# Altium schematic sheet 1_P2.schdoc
size 426 x 302 mm
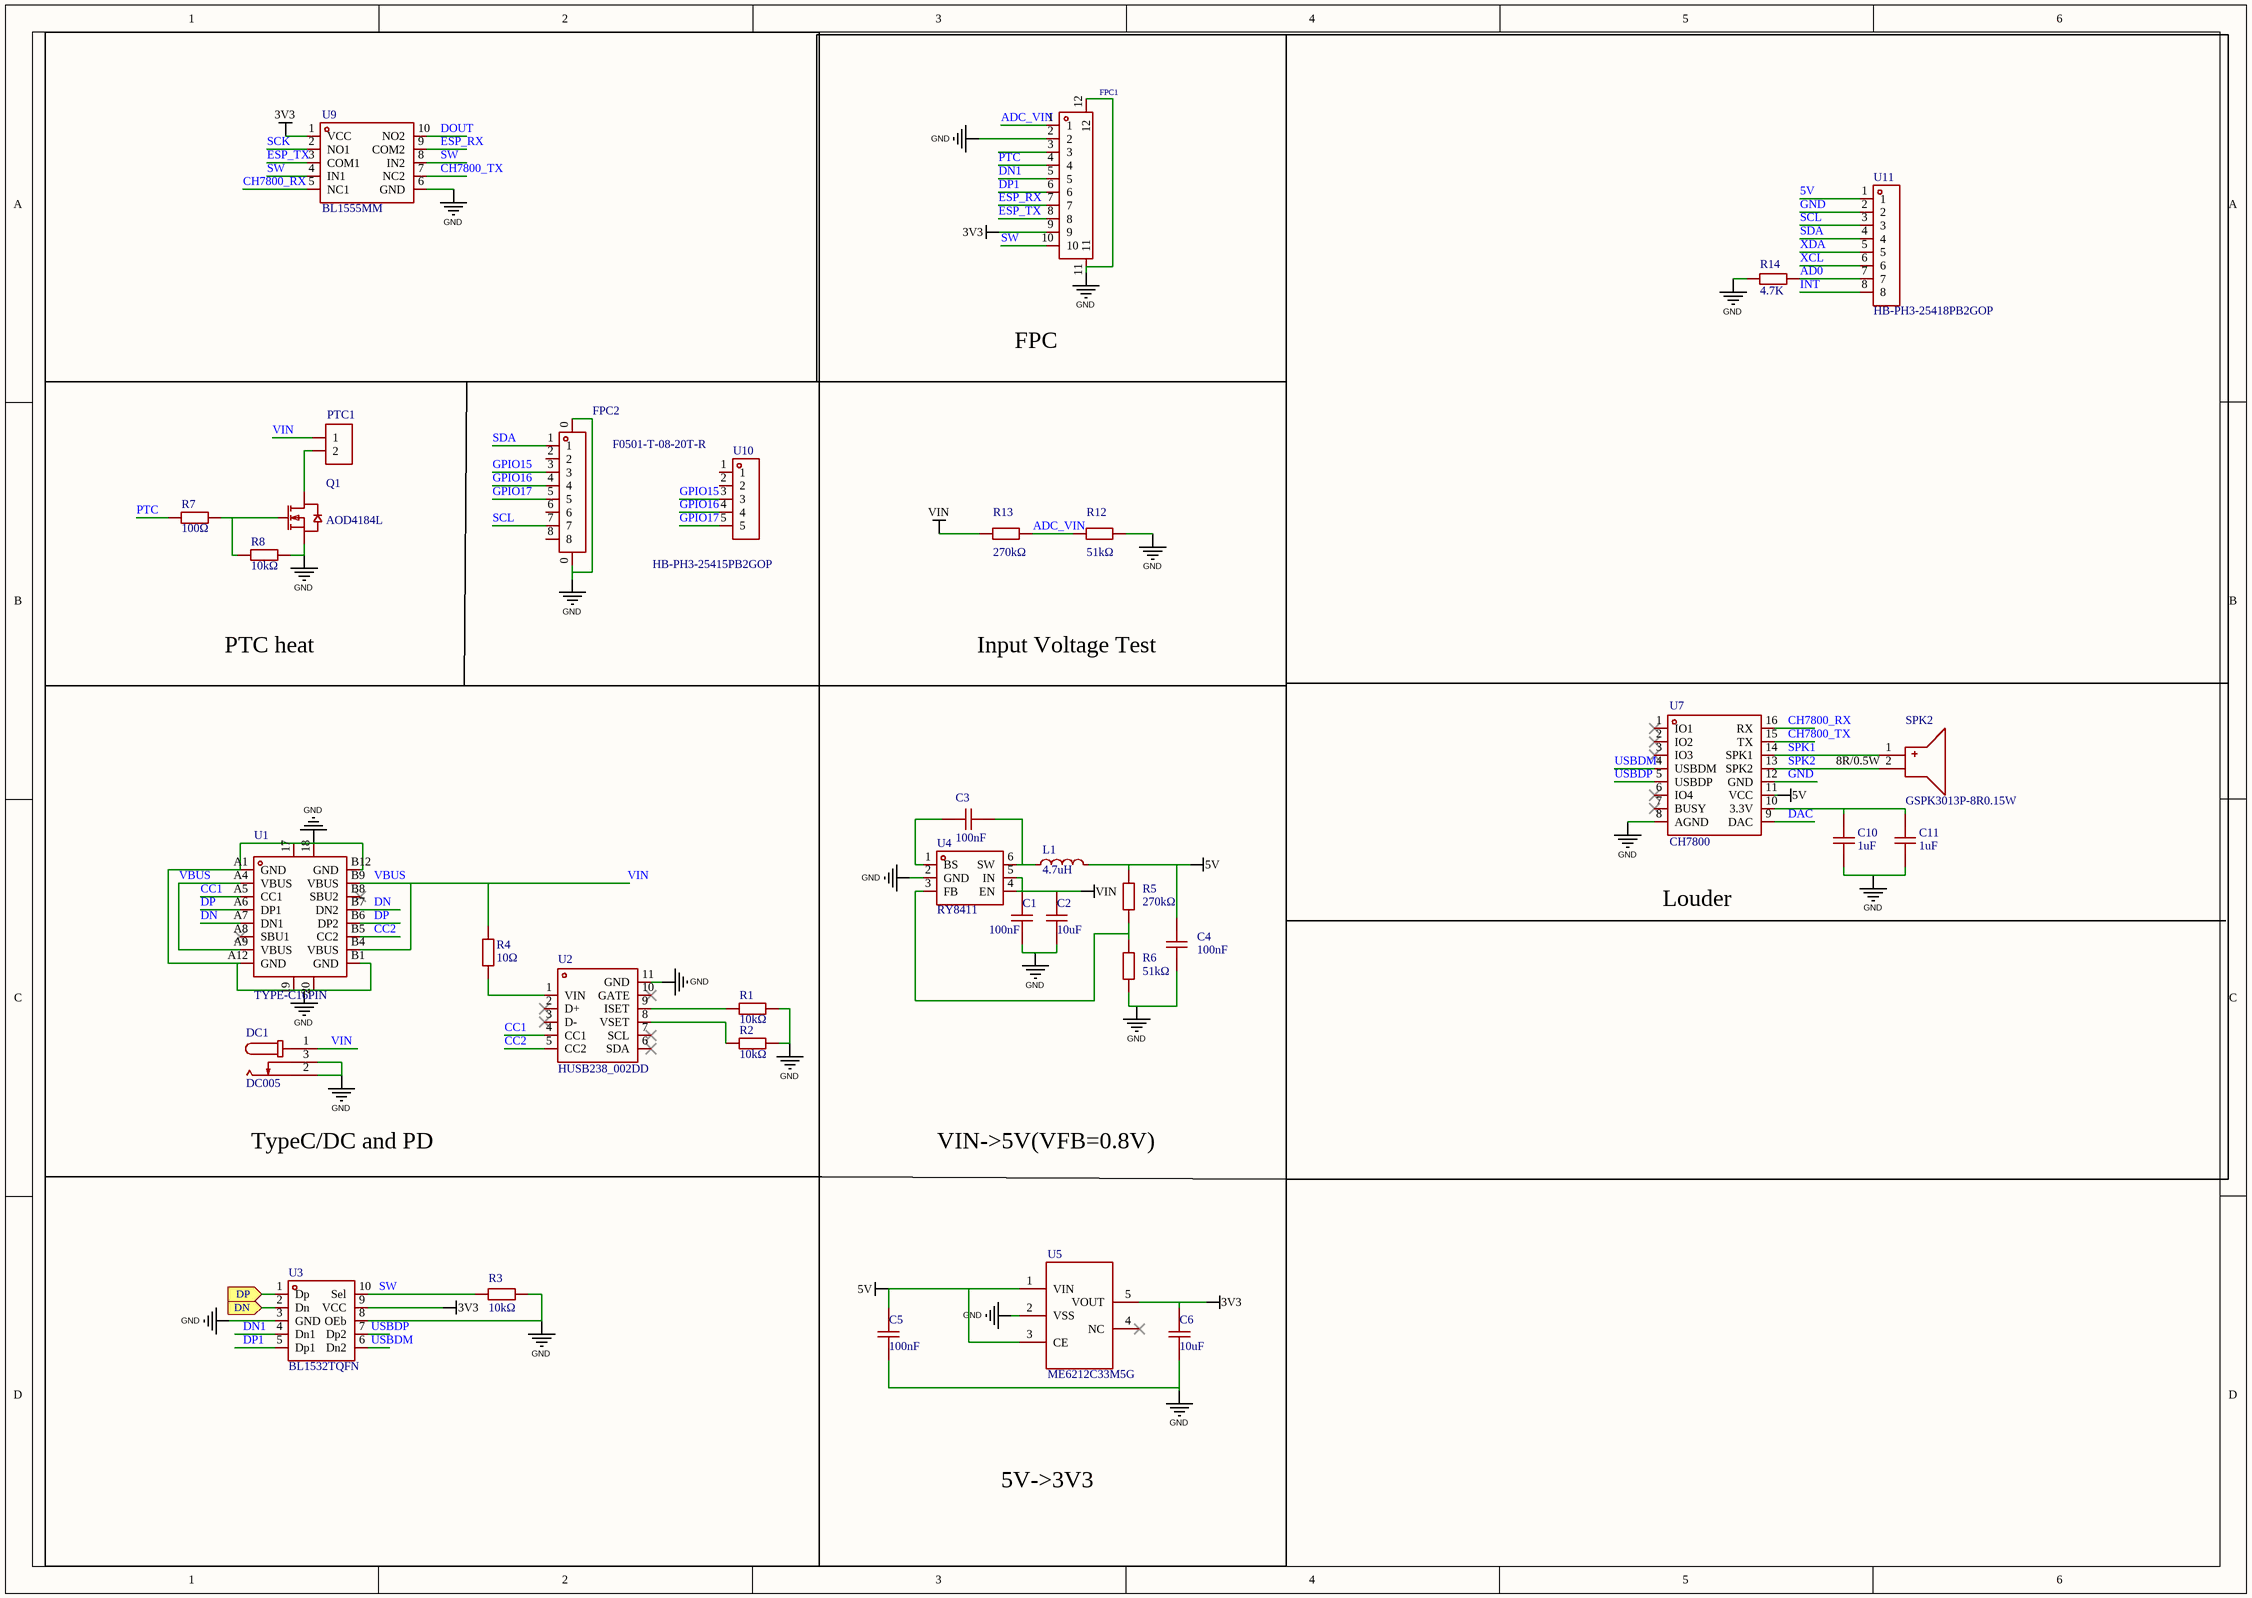
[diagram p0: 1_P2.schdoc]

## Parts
C1  100nF  [C0603]
C2  10uF  [C0603]
C3  100nF  [C0603]
C4  100nF  [C0603]
C5  100nF  [C0603]
C6  10uF  [C0603]
C10  1uF  [C0603]
C11  1uF  [C0603]
DC1  DC005  [DC-IN-TH_DC005]
FPC1  F0501-T-10-20T-R  [FPC-SMD_F0501-T-10-20T-R]  (value not drawn)
FPC2  F0501-T-08-20T-R  [FPC-SMD_8P-P0.50_L4.4-W9.6]
L1  4.7uH  [IND-SMD_L3.5-W3.0]
PTC1  (no value)  [HDR-TH_2P-P2.54-V-F]
Q1  AOD4184L  [TO-252-2_L6.6-W6.1-P4.57-LS9.9-TL-CW]
R1  10kΩ  [R0603]
R2  10kΩ  [R0603]
R3  10kΩ  [R0603]
R4  10Ω  [R0603]
R5  270kΩ  [R0603]
R6  51kΩ  [R0603]
R7  100Ω  [R0603]
R8  10kΩ  [R0603]
R12  51kΩ  [R0603]
R13  270kΩ  [R0603]
R14  4.7K  [R0603]
SPK2  GSPK3013P-8R0.15W  [SPK-TH_BD30.0-P15.00-D0.8-L-RD]
U1  TYPE-C16PIN  [USB-C-SMD_TYPE-C16PIN]
U2  HUSB238_002DD  [DFN-10_L3.0-W3.0-P0.50-BL-EP2.5]
U3  BL1532TQFN  [QFN-10_L1.4-W1.8-P0.40-BL]
U4  RY8411  [SOT-23-6_L2.9-W1.6-P0.95-LS2.8-TL]
U5  ME6212C33M5G  [SOT-23-5_L3.0-W1.7-P0.95-LS2.8-BL]
U7  CH7800  [SOP-16_L9.9-W3.9-P1.27-LS6.0-BL]
U9  BL1555MM  [MSOP-10_L3.0-W3.0-P0.50-LS5.0-BL]
U10  HB-PH3-25415PB2GOP  [HDR-TH_5P-P2.54-V-M]
U11  HB-PH3-25418PB2GOP  [HDR-TH_8P-P2.54-V-M]

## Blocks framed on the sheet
FPC: FPC1
PTC heat: FPC2 PTC1 Q1 R7 R8 U10
Input Voltage Test: R12 R13
TypeC/DC and PD: DC1 R1-R4 U1-U3
Louder: C10 C11 SPK2 U7

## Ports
DN (in), DP (in)

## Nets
3V3: C6.1 FPC1.9 U3.9(VCC) U5.5(VOUT) U9.1(VCC)
5V: C4.1 C5.1 L1.2 R5.2 U5.1(VIN) U5.3(CE) U7.11(VCC) U11.1
GND: C1.2 C2.2 C4.2 C5.2 C6.2 C10.1 C11.1 DC1.2 DC1.3 FPC1.2 FPC1.11 FPC1.12 FPC2.0 Q1.3(S) R1.2 R2.2 R3.1 R6.1 R8.2 R12.2 R14.1 U1.17 U1.18 U1.19 U1.20 U1.A1(GND) U1.A12(GND) U1.B1(GND) U1.B12(GND) U2.11(GND) U3.3(GND) U3.8(OEb) U4.2(GND) U5.2(VSS) U7.8(AGND) U7.12(GND) U9.6(GND) U11.2
VBUS: C1.1 C2.1 DC1.1 PTC1.1 R4.2 R13.1 U1.A4(VBUS) U1.A9(VBUS) U1.B4(VBUS) U1.B9(VBUS) U4.4(EN) U4.5(IN)  [also labelled VIN]
AD0: R14.2 U11.7
ADC_VIN: FPC1.1 R12.1 R13.2
CC1: U1.A5(CC1) U2.4(CC1)
CC2: U1.B5(CC2) U2.5(CC2)
CH7800_RX: U7.16(RX) U9.5(NC1)
CH7800_TX: U7.15(TX) U9.7(NC2)
DAC: U7.9(DAC)
DN: U3.2(Dn) ; port DN
DN: U1.A7(DN1) U1.B7(DN2)  [a separate net that carries the same name]
DN1: FPC1.5 U3.4(Dn1)
DOUT: U9.10(NO2)
DP: U3.1(Dp) ; port DP
DP: U1.A6(DP1) U1.B6(DP2)  [a separate net that carries the same name]
DP1: FPC1.6 U3.5(Dp1)
ESP_RX: FPC1.7 U9.9(COM2)
ESP_TX: FPC1.8 U9.3(COM1)
GPIO15: FPC2.3 U10.3
GPIO16: FPC2.4 U10.4
GPIO17: FPC2.5 U10.5
INT: U11.8
PTC: FPC1.4 R7.1
SCK: U9.2(NO1)
SCL: FPC2.7 U11.3
SDA: FPC2.1 U11.4
SPK1: SPK2.1(+) U7.14(SPK1)
SPK2: SPK2.2(-) U7.13(SPK2)
SW: FPC1.10 R3.2 U3.10(Sel) U9.4(IN1) U9.8(IN2)
USBDM: U3.6(Dn2) U7.4(USBDM)
USBDP: U3.7(Dp2) U7.5(USBDP)
XCL: U11.6
XDA: U11.5
NetC3_1: C3.1 U4.1(BS)
NetC3_2: C3.2 L1.1 U4.6(SW)
NetC10_2: C10.2 C11.2 U7.10(3.3V)
NetPTC1_2: PTC1.2 Q1.2(D)
NetQ1_1: Q1.1(G) R7.2 R8.1
NetR1_1: R1.1 U2.9(ISET)
NetR2_1: R2.1 U2.8(VSET)
NetR4_1: R4.1 U2.1(VIN)
NetR5_1: R5.1 R6.2 U4.3(FB)

Not connected (* = marked no-connect by the designer): FPC1 3; FPC2 2 6 8; U1 A8(SBU1)* B8(SBU2)*; U2 2(D+)* 3(D-)* 6(SDA)* 7(SCL)* 10(GATE)*; U5 4(NC)*; U7 1(IO1)* 2(IO2)* 3(IO3)* 6(IO4)* 7(BUSY)*; U10 1 2

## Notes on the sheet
- (near SPK2) 8R/0.5W
- VIN->5V(VFB=0.8V)
- 5V->3V3

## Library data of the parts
C1 C3-C5 = CGA0603X7R104K500JT: Manufacturer: HRE(芯声); Symbol: CapAcitance; Add into BOM: yes; Tolerance: ±10%; Voltage Rated: 50V; Temperature Coefficient: X7R
C2 C6 = CL10A106KP8NNNC: Manufacturer: SAMSUNG(三星); Symbol: CapAcitance; Add into BOM: yes; Tolerance: ±10%; Voltage Rated: 10V; Temperature Coefficient: X5R
C10 C11 = CL10A105KA8NNNC: Manufacturer: SAMSUNG(三星); Symbol: CapAcitance; Add into BOM: yes; Tolerance: ±10%; Voltage Rated: 25V; Temperature Coefficient: X5R
DC1 = DC005: Manufacturer: SHOU HAN(首韩); Symbol: DC005_C431533; Add into BOM: yes; Connector Type: DC电源插座; Inside Contact Diameter: 2mm; Outside Contact Diameter: 6.3mm; Current Rating (Max): 500mA; Voltage Rating (Max): 30V
FPC1 = F0501-T-10-20T-R: Manufacturer: XFCN(兴飞); Add into BOM: yes; Pitch: 0.5mm; Number of Contacts: 10P; Locking Feature: 抽屉式
FPC2 = F0501-T-08-20T-R: Manufacturer: XFCN(兴飞); Add into BOM: yes; Locking Feature: 抽屉式; Number of Contacts: 8P; Pitch: 0.5mm
L1 = CD32-4R7M 4.7UH: Manufacturer: DMBJ(振宝佳); Add into BOM: yes; Tolerance: ±20%; Rated Current: 1.5A; DC Resistance (DCR): 137mΩ
PTC1 = HDR-F_2.54_1x2P: Manufacturer: BOOMELE(博穆精密); Manufacturer Part: 2.54-1*2P母; Symbol: Header-Female-2.54_1x2; Convert to PCB: yes
Q1 = AOD4184L: Manufacturer: AOS; Add into BOM: yes; Type: 1个N沟道; Drain Source Voltage (Vdss): 40V; Continuous Drain Current (Id): 50A; Drain Source On Resistance (RDS(on)@Vgs,Id): 8mΩ@10V,20A; Power Dissipation (Pd): 50W; Gate Threshold Voltage (Vgs(th)@Id): 3V@250uA
R1-R3 R8 = 0603WAF1002T5E: Manufacturer: UNI-ROYAL(厚声); Symbol: 电阻; Add into BOM: yes; Tolerance: ±1%; Power(Watts): 100mW; Overload Voltage (Max): 75V; Temperature Coefficient: ±100ppm/℃
R4 = 0603WAF100JT5E: Manufacturer: UNI-ROYAL(厚声); Symbol: 电阻; Add into BOM: yes; Tolerance: ±1%; Power(Watts): 100mW; Overload Voltage (Max): 75V; Temperature Coefficient: ±400ppm/℃
R5 = FRC0603F2703TS: Manufacturer: FOJAN(富捷); Symbol: 电阻; Add into BOM: yes; Tolerance: ±1%; Power(Watts): 100mW; Overload Voltage (Max): 75V; Temperature Coefficient: ±100ppm/℃
R6 R12 = 0603WAF5102T5E: Manufacturer: UNI-ROYAL(厚声); Symbol: 电阻; Add into BOM: yes; Tolerance: ±1%; Power(Watts): 100mW; Overload Voltage (Max): 75V; Temperature Coefficient: ±100ppm/℃
R7 = 0603WAF1000T5E: Manufacturer: UNI-ROYAL(厚声); Symbol: 电阻; Add into BOM: yes; Tolerance: ±1%; Power(Watts): 100mW; Overload Voltage (Max): 75V; Temperature Coefficient: ±200ppm/℃
R13 = 0603WAF2703T5E: Manufacturer: UNI-ROYAL(厚声); Symbol: 电阻; Add into BOM: yes; Tolerance: ±1%; Power(Watts): 100mW; Overload Voltage (Max): 75V; Temperature Coefficient: ±100ppm/℃
R14 = Res_0603: Symbol: 电阻; Convert to PCB: yes
SPK2 = GSPK3013P-8R0.15W: Manufacturer: INGHAi(赢海); Add into BOM: yes
U1 = TYPE-C16PIN: Manufacturer: SHOU HAN(首韩); Symbol: TYPE-C16PIN母座 板上四脚三次MOLDING; Add into BOM: yes; Connector Type: Type-C; Gender: 母; Number of Contacts: 16P; Number of Ports: 1; Current Rating - Power (Max): 3A; Rated Voltage (Max): 30V; Connect-Disconnect Life: 1万次; Core Colour: 黑色
U2 = HUSB238_002DD: Manufacturer: Hynetek(慧能泰); Symbol: HUSB238-002D; Add into BOM: yes
U3 = BL1532TQFN: Manufacturer: BL(上海贝岭); Add into BOM: yes
U4 = RY8411_C2935411: Manufacturer: RYCHiP(蕊源); Add into BOM: yes
U5 = ME6212C33M5G: Manufacturer: MICRONE(南京微盟); Add into BOM: yes; Output Type: 固定; Maximum Input Voltage: 6V; Output Voltage: 3.3V; MAX Output Current: 350mA; Power Supply Rejection Ratio (PSRR): 65dB; Dropout Voltage: 260mV@(200mA); Output Polarity: 正极; Number of Outputs: 1
U7 = CH7800: Add into BOM: yes
U9 = BL1555MM: Manufacturer: BL(上海贝岭); Add into BOM: yes
U10 = HB-PH3-25415PB2GOP: Manufacturer: HANBO(汉博); Add into BOM: yes; Pin Structure: 1x5P; Pitch: 2.54mm; Circluar Pins/Square Pins: 方针; Current Rating (Max): 3A; Voltage Rating (Max): 250V; Soldering Temperature(Max): 260℃
U11 = HB-PH3-25418PB2GOP: Manufacturer: HANBO(汉博); Add into BOM: yes; Pin Structure: 1x8P; Pitch: 2.54mm; Circluar Pins/Square Pins: 方针; Current Rating (Max): 3A; Voltage Rating (Max): 250V; Soldering Temperature(Max): 260℃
